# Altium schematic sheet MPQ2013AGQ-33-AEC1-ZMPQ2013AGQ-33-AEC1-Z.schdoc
size 127 x 101 mm
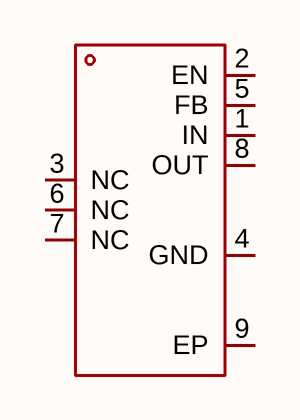
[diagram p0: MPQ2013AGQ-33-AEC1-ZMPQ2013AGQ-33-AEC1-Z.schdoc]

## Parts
U?  mpq2013agq-33-aec1-z  [QFN-8_L3.0-W3.0-P0.65-TR-EP]  (value not drawn)

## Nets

Not connected (* = marked no-connect by the designer): U? 1(IN) 2(EN) 3(NC) 4(GND) 5(FB) 6(NC) 7(NC) 8(OUT) 9(EP)

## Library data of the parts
U? = mpq2013agq-33-aec1-z: 输出极性:正极;工作电压:40V;输出电压:3.3V;输出电流:150mA;电源纹波抑制比(PSRR):-;输出类型:固定;; Manufacturer: MPS(芯源); AddInBom: yes; ModelId: 722a1ab727144a719165e391d1e7c353; ModelTransform: 118.11,118.8974,0,180,0,0,0,0,0; Output Configuration: 正极; Voltage - Supply: 40V; Output Voltage: 3.3V; Output Current: 150mA; Voltage Dropout: 700mV@(150mA); standby current: 3.3uA; Output Type: 固定; Number of Outputs: 1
